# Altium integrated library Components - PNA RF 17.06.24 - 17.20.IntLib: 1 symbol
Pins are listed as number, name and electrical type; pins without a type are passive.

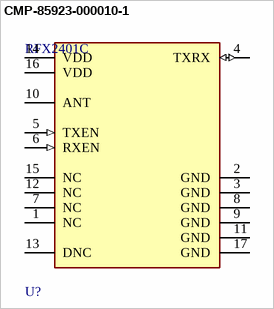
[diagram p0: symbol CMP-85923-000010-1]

## CMP-85923-000010-1
designator U?, comment RFX2401C
IC FRONT END WLAN/ZIGBEE 16QFN; Frequency: 2.5GHz
footprint FP-RFX2401C-MFG
footprint FP-RFX2401C-IPC_C
footprint FP-RFX2401C-IPC_B
footprint FP-RFX2401C-IPC_A
pins: 1 NC, 2 GND (power), 3 GND (power), 4 TXRX (io), 5 TXEN (in), 6 RXEN (in), 7 NC, 8 GND (power), 9 GND (power), 10 ANT, 11 GND (power), 12 NC, 13 DNC, 14 VDD (power), 15 NC, 16 VDD (power), 17 GND (power)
